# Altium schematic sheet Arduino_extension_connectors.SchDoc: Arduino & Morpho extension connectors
size A4; Date: Not used; ApprovedBy: Not used; CheckedBy: Not used; Author: Not used; CompanyName: STMicroelectronics; DrawnBy: Not used; Engineer: Not used; Organization: Not used; Address1: Not used; Address2: Not used; Address3: Not used; Address4: Not used; DocumentNumber: 5; Revision: Not used; SheetNumber: 5; SheetTotal: 8
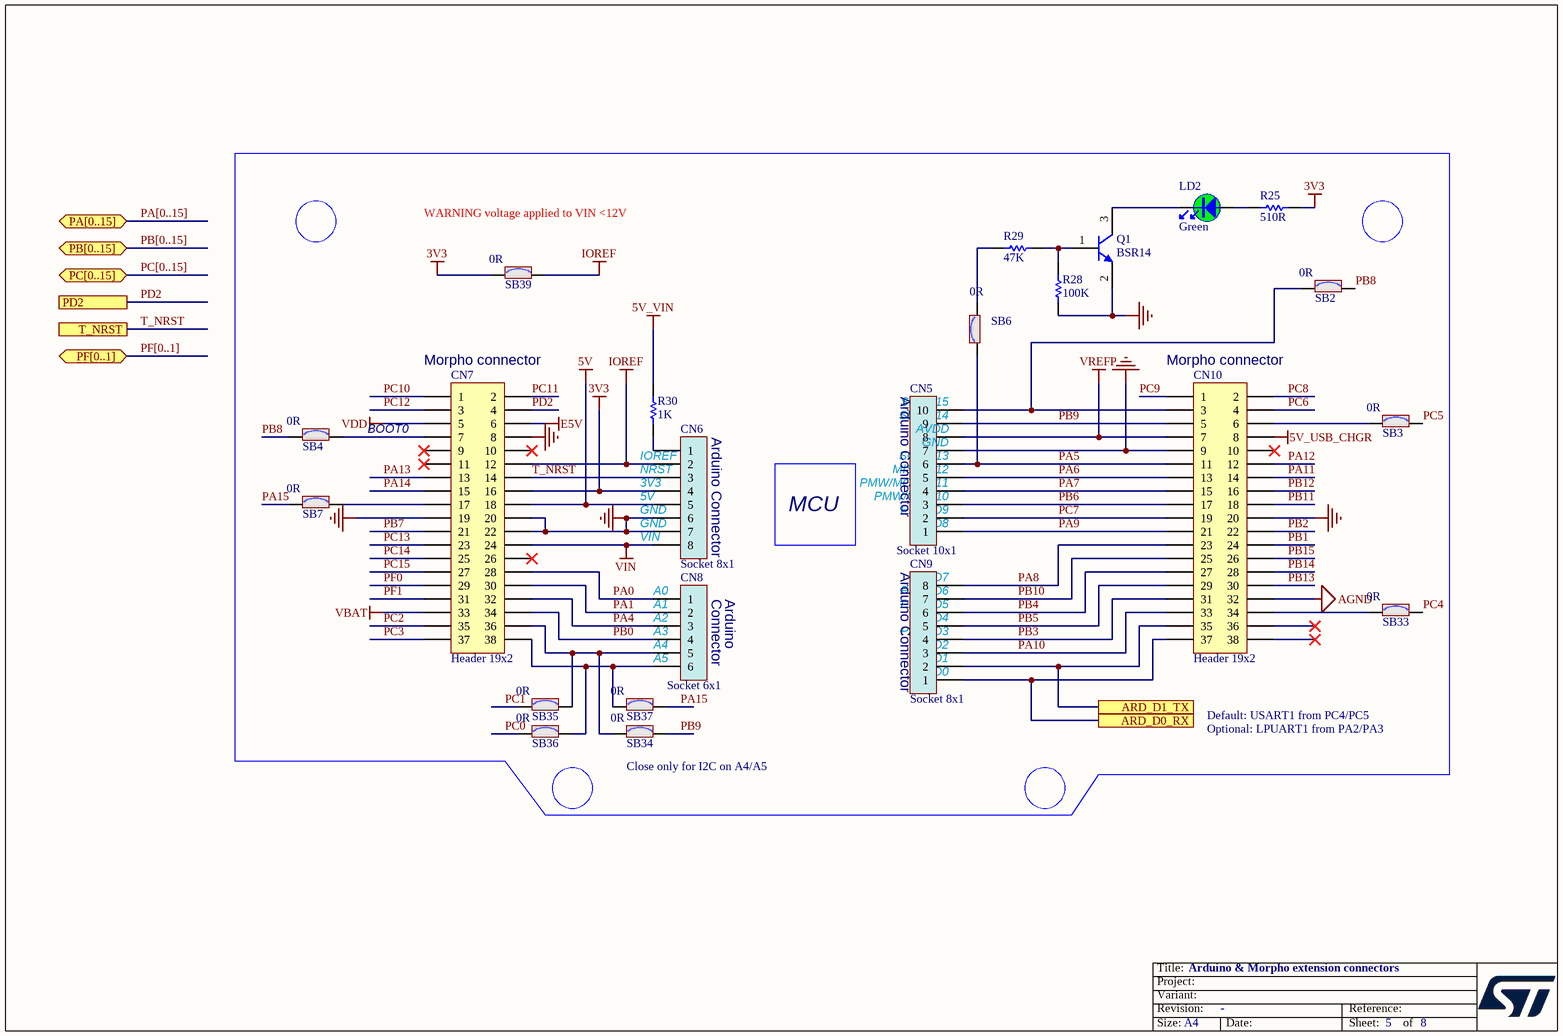
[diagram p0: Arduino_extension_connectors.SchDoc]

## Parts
CN5  value Socket 10x1  [CON_SAMTEC_SSW-110-03-X-S]
CN6  value Socket 8x1  [CON_SAMTEC_SSW-108-03-X-S]
CN7  value Header 19x2  [CON_SAMTEC_TSW-119-09-X-D]
CN8  value Socket 6x1  [CON_SAMTEC_SSW-106-03-X-S]
CN9  value Socket 8x1  [CON_SAMTEC_SSW-108-03-X-S]
CN10  value Header 19x2  [CON_SAMTEC_TSW-119-09-X-D]
LD2  value Green  [LED_0603_GREEN]  (hidden comment: LED_green)
Q1  value BSR14  [NPN_SOT23]
R25  value 510R  [R0603]
R28  value 100K  [R0603]
R29  value 47K  [R0603]
R30  value 1K  [R0603]
SB2  value 0R  [SOLDER-BRIDGE_R0603-0R]
SB3  value 0R  [SOLDER-BRIDGE_R0603-0R]
SB4  value 0R  [SOLDER-BRIDGE_R0603-0R]
SB6  value 0R  [SOLDER-BRIDGE_R0603-0R]
SB7  value 0R  [SOLDER-BRIDGE_R0603-0R]
SB33  value 0R  [SOLDER-BRIDGE_R0603-0R]
SB34  value 0R  [SOLDER-BRIDGE_R0603-0R]
SB35  value 0R  [SOLDER-BRIDGE_R0603-0R]
SB36  value 0R  [SOLDER-BRIDGE_R0603-0R]
SB37  value 0R  [SOLDER-BRIDGE_R0603-0R]
SB39  value 0R  [SOLDER-BRIDGE_R0603-0R]

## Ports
ARD_D0_RX, ARD_D1_TX, PA[0..15] (bidir), PB[0..15] (bidir), PC[0..15] (bidir), PD2, PF[0..1] (bidir), T_NRST

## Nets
3V3: CN6.4 CN7.16 R25.1 SB39.1
5V: CN6.5 CN7.18
5V_USB_CHGR: CN10.8
5V_VIN: R30.2
AGND: CN10.32
E5V: CN7.6
GND: CN5.7 CN6.6 CN6.7 CN7.8 CN7.19 CN7.20 CN7.22 CN10.9 CN10.20 Q1.2(E) R28.1
IOREF: CN6.2 CN7.12 SB39.2
VBAT: CN7.33
VDD: CN7.5
VIN: CN6.8 CN7.24
VREFP: CN5.8 CN10.7
ARD_D0_RX: CN9.1 CN10.37 ; port ARD_D0_RX
ARD_D1_TX: CN9.2 CN10.35 ; port ARD_D1_TX
PA0: CN7.28 CN8.1
PA1: CN7.30 CN8.2
PA4: CN7.32 CN8.3
PA5: CN5.6 CN10.11 SB6.1
PA6: CN5.5 CN10.13
PA7: CN5.4 CN10.15
PA8: CN9.8 CN10.23
PA9: CN5.1 CN10.21
PA10: CN9.3 CN10.33
PA11: CN10.14
PA12: CN10.12
PA13: CN7.13
PA14: CN7.15
PA15: SB7.1 SB37.2
PB0: CN7.34 CN8.4
PB1: CN10.24
PB2: CN10.22
PB3: CN9.4 CN10.31
PB4: CN9.6 CN10.27
PB5: CN9.5 CN10.29
PB6: CN5.3 CN10.17
PB7: CN7.21
PB8: SB2.2 SB4.1
PB9: CN5.9 CN10.5 SB34.2
PB10: CN9.7 CN10.25
PB11: CN10.18
PB12: CN10.16
PB13: CN10.30
PB14: CN10.28
PB15: CN10.26
PC0: SB36.1
PC1: SB35.1
PC2: CN7.35
PC3: CN7.37
PC4: SB33.2
PC5: SB3.2
PC6: CN10.4
PC7: CN5.2 CN10.19
PC8: CN10.2
PC9: CN10.1
PC10: CN7.1
PC11: CN7.2
PC12: CN7.3
PC13: CN7.23
PC14: CN7.25
PC15: CN7.27
PD2: CN7.4 ; port PD2
PF0: CN7.29
PF1: CN7.31
T_NRST: CN6.3 CN7.14 ; port T_NRST
NetCN5_10: CN5.10 CN10.3 SB2.1
NetCN6_1: CN6.1 R30.1
NetCN7_7: CN7.7 SB4.2
NetCN7_17: CN7.17 SB7.2
NetCN7_36: CN7.36 CN8.5 SB34.1 SB35.2
NetCN7_38: CN7.38 CN8.6 SB36.2 SB37.1
NetCN10_6: CN10.6 SB3.1
NetCN10_34: CN10.34 SB33.1
NetLD2_1: LD2.1 R25.2
NetLD2_2: LD2.2 Q1.3(C)
NetQ1_1: Q1.1(B) R28.2 R29.2
NetR29_1: R29.1 SB6.2

Not connected (* = marked no-connect by the designer): CN7 9* 10* 11* 26*; CN10 10* 36* 38*

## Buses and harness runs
bus PA[0..15] = port PA[0..15]
bus PB[0..15] = port PB[0..15]
bus PC[0..15] = port PC[0..15]
bus PF[0..1] = port PF[0..1]

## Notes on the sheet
- WARNING voltage applied to VIN <12V
- (near CN7) Morpho connector
- (near CN10) Morpho connector
- (near CN7) BOOT0
- (near CN6) Arduino Connector
- (near CN5) Arduino Connector
- (near CN5) SDA/D14
- (near CN5) SCL/D15
- (near CN5) AVDD
- (near CN5) GND
- (near CN6) GND
- (near CN6) 5V
- (near CN6) 3V3
- (near CN6) NRST
- (near CN6) IOREF
- MCU
- (near CN5) PMW/D9
- (near CN5) PMW/CS/D10
- (near CN5) SCK/D13
- (near CN5) MISO/D12
- (near CN5) PMW/MOSI/D11
- (near CN6) VIN
- (near CN9) Arduino Connector
- (near CN9) D7
- (near CN5) D8
- (near CN8) A0
- (near CN8) A1
- (near CN8) A2
- (near CN8) A3
- (near CN8) A4
- (near CN8) Connector
- (near CN8) Arduino
- (near CN9) D2
- (near CN9) D4
- (near CN9) PMW/D3
- (near CN9) PMW/D5
- (near CN9) PMW/D6
- (near CN8) A5
- (near CN9) RX/D0
- (near CN9) TX/D1
- (near SB34) Close only for I2C on A4/A5
- Default: USART1 from PC4/PC5
  Optional: LPUART1 from PA2/PA3

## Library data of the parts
CN5 = MCD-00262: Socket, 10x1, 2.54mm, VR, TH, Height 8.51mm/10mm; Manufacturer_Part_Number: SSW-110-03-G-S; Manufacturer: SAMTEC; Part_Type: Connector; Full_Alternate_Internal_Part_Number: MCD-02397; Part_Preference: Recommended; Provided_By: SUBCO; Component_Country_Of_Origin: China, Costa Rica, Malaysia, USA, Vietnam; ID: 2609; Order_Code_RS: 207-9189; ShowFields: YES
CN6 CN9 = MCD-00261: Socket, 8x1, 2.54mm, VR, TH, Height 8.51mm/10mm; Manufacturer_Part_Number: SSW-108-03-G-S; Manufacturer: SAMTEC; Part_Type: Connector; Part_Preference: Recommended; Partial_Alternate_Internal_Part_Number: MCD-02396; Provided_By: SUBCO; Component_Country_Of_Origin: China, Costa Rica, Malaysia, USA, Vietnam; ID: 2607; ShowFields: YES
CN7 CN10 = MCD-00213: Header, 19x2, 2,54mm, VR, TH, Height 5.84mm/10.16mm; Manufacturer_Part_Number: TSW-119-09-G-D; Manufacturer: SAMTEC; Part_Type: Connector; Part_Preference: Recommended; Partial_Alternate_Internal_Part_Number: MCD-00213, MCD-02394, MCD-03736, MCD-03787, MCD-03997, MCD-04171, MCD-04274; Provided_By: SUBCO; Component_Country_Of_Origin: China, Costa Rica, Malaysia, USA, Vietnam; ID: 2656; ShowFields: YES
CN8 = MCD-00260: Socket, 6x1, 2.54mm, VR, TH, Height 8.51mm/10mm; Manufacturer_Part_Number: SSW-106-03-G-S; Manufacturer: SAMTEC; Part_Type: Connector; Part_Preference: Recommended; Partial_Alternate_Internal_Part_Number: MCD-02395; Provided_By: SUBCO; Component_Country_Of_Origin: China, Costa Rica, Malaysia, USA, Vietnam; ID: 2606; ShowFields: YES
LD2 = MCD-02900: LED, Green, 2V, 20mA, 0603; Part_Type: Display; Part_Preference: Recommended; Manufacturer: EVERLIGHT; Manufacturer_Part_Number: 19-213SYGC/S530-E2/5T; Full_Alternate_Internal_Part_Number: MCD-00320; Partial_Alternate_Internal_Part_Number: MCD-00050; ShowFields: YES; ID: 5016; Component_Country_Of_Origin: China
Q1 = MCD-00073: NPN Bipolar Transistor; Manufacturer: ON SEMICONDUCTOR; Alternate_Manufacturer_Part_Number: MMBT2222LT1G / MMBT2222ALT1G / MMBT2222ALT3G; Part_Preference: Recommended; Partial_Alternate_Internal_Part_Number: MCD-01737, MCD-03305, MCD-02988; ECCN_US: EAR99; ECCN_EU: NEC; Provided_By: SUBCO; Component_Country_Of_Origin: Unknown; ID: 2519; ShowFields: YES
R25 = MCD-00225: Resistor,510R,0603,1%,1/10W; Manufacturer_Part_Number: RC0603FR-07510RL; Manufacturer: YAGEO; Part_Preference: Recommended; ECCN_US: EAR99; ECCN_EU: NEC; Provided_By: SUBCO; Component_Country_Of_Origin: China; ID: 2644; ShowFields: YES
R28 = MCD-00223: Resistor,100K,0603,1%,1/10W; Manufacturer_Part_Number: RC0603FR-07100KL; Manufacturer: YAGEO; Part_Preference: Recommended; Provided_By: Subcon; Initial_Board_Reference: MB1319; Component_Country_Of_Origin: China; ID: 2647; ShowFields: YES
R29 = MCD-00222: Resistor,47K,0603,1%,1/10W; Manufacturer_Part_Number: RC0603FR-0747KL; Manufacturer: YAGEO; Part_Preference: Recommended; ECCN_US: EAR99; ECCN_EU: NEC; Provided_By: SUBCO; Component_Country_Of_Origin: China; ID: 2645; ShowFields: YES
R30 = MCD-00070: Resistor,1K,0603,1%,1/10W; Manufacturer_Part_Number: RC0603FR-071KL; Manufacturer: YAGEO; Part_Preference: Recommended; Provided_By: Subcon; Initial_Board_Reference: MB1274; Component_Country_Of_Origin: China; ID: 2522; Order_Code_RS: 9238484RL; ShowFields: YES
SB2-SB4 SB6 SB7 SB33-SB37 SB39 = MCD-00071: Solder Bridge ON; Part_Type: Resistor; Manufacturer_Part_Number: RC0603JR-070RL; Manufacturer: YAGEO; Manufacturer_HQ_COO: Unknown; Part_Preference: Recommended; Provided_By: SUBCO; Component_Country_Of_Origin: China; ID: 2521; Order_Code_RS: 199-5647; ShowFields: YES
